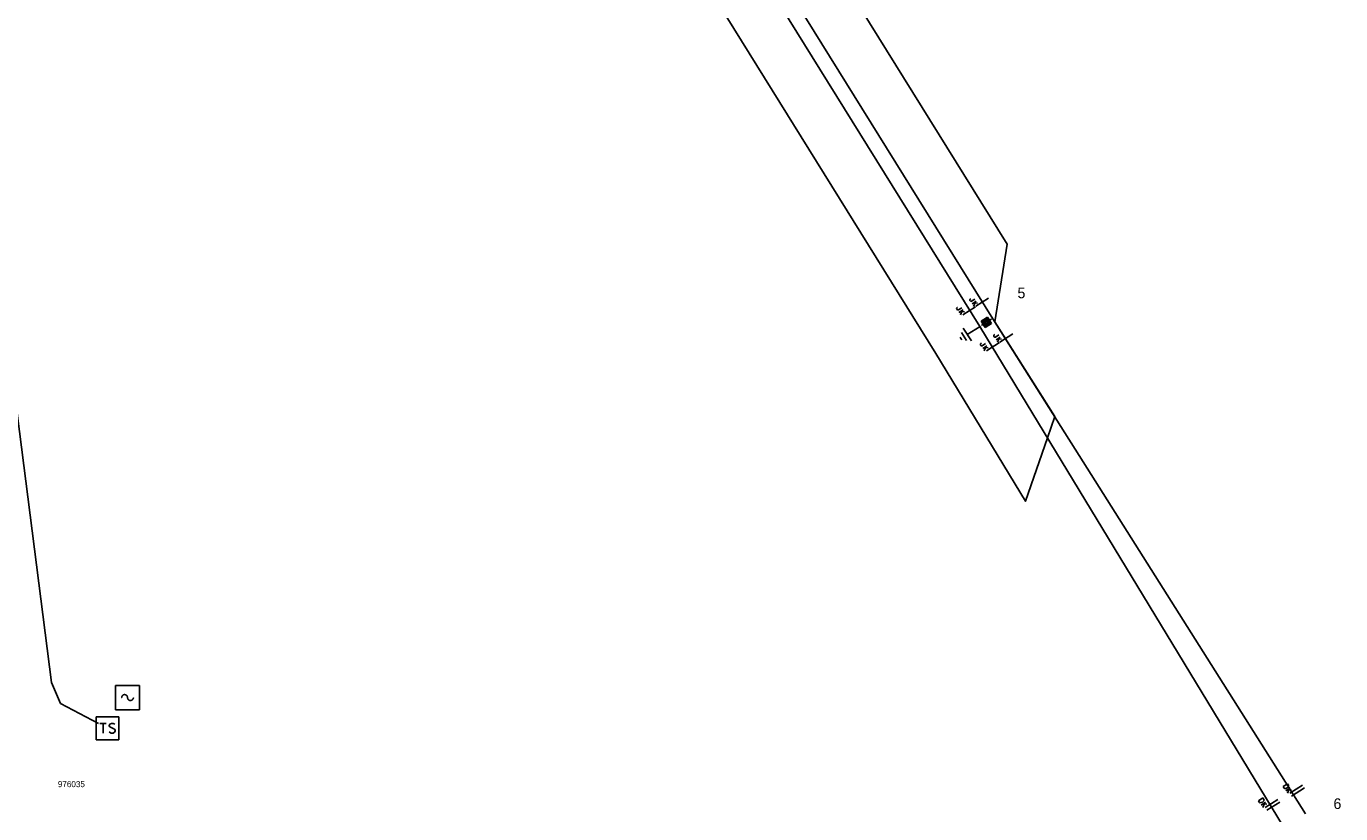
# Model space of a CAD drawing. Extents: x -788491 to -785797, y -1154753 to -1152002.
# Drawn here: x -787504.8 to -787287.9, y -1153999.5 to -1153869.5 of the extents above; entities that cross this region are included whole.
import ezdxf

# ---------------------------------------------------------------- set-up
doc = ezdxf.new("R2010")
doc.units = 0
for name, color, linetype in [('Vrstva 1', 7, 'Continuous'), ('Vrstva 13', 7, 'Continuous'), ('Vrstva 14', 7, 'Continuous'), ('Vrstva 15', 7, 'Continuous'), ('Vrstva 18', 7, 'Continuous'), ('Vrstva 2', 7, 'Continuous'), ('Vrstva 25', 7, 'Continuous'), ('Vrstva 26', 7, 'Continuous'), ('Vrstva 34', 7, 'Continuous'), ('Vrstva 35', 7, 'Continuous'), ('Vrstva 5', 7, 'Continuous'), ('Vrstva 6', 7, 'Continuous')]:
    doc.layers.add(name, color=color, linetype=linetype)

# ---------------------------------------------------------------- blocks, each defined once
blk = doc.blocks.new('VN850')
at = {"layer": 'Vrstva 15'}
for points in [[(-0.56, 1.43), (-0.56, -1.07)], [(-0.01, 1.43), (-0.01, -1.07)], [(-2.09, -0.54), (-1.78, -0.54)], [(-2.09, -1.41), (-2.09, -0.54)], [(-1.78, -1.41), (-2.09, -1.41)], [(-1.78, -0.54), (-1.66, -0.6)], [(-1.67, -1.35), (-1.78, -1.41)], [(-1.59, -1.2), (-1.67, -1.35)], [(-1.66, -0.6), (-1.59, -0.75)], [(-1.59, -0.75), (-1.55, -0.96)], [(-1.55, -0.96), (-1.59, -1.2)], [(-1.26, -0.54), (-1.26, -1.41)], [(-0.85, -0.54), (-1.26, -1.09)], [(-1.13, -0.92), (-0.77, -1.41)]]:
    blk.add_lwpolyline(points, dxfattribs=at)
blk = doc.blocks.new('VN840')
at = {"layer": 'Vrstva 15'}
for points in [[(-0.01, 1.41), (-0.01, -1.09)], [(-1.51, -1.24), (-1.51, -1.15)], [(-1.48, -1.35), (-1.51, -1.24)], [(-1.33, -1.42), (-1.48, -1.35)], [(-1.27, -1.42), (-1.33, -1.42)], [(-1.13, -1.35), (-1.27, -1.42)], [(-1.09, -1.24), (-1.13, -1.35)], [(-1.09, -0.59), (-1.09, -1.24)], [(-0.68, -0.59), (-0.68, -1.42)], [(-0.68, -1.11), (-0.27, -0.59)], [(-0.54, -0.94), (-0.2, -1.42)]]:
    blk.add_lwpolyline(points, dxfattribs=at)
blk = doc.blocks.new('VN810')
at = {"layer": 'Vrstva 14'}
for points in [[(0, -1.25), (0, -3.75)], [(1.25, -3.75), (-1.25, -3.75)], [(0.77, -4.37), (-0.8, -4.37)], [(0, -5), (-0.25, -5)], [(0.27, -5), (0, -5)]]:
    blk.add_lwpolyline(points, dxfattribs=at)
blk = doc.blocks.new('VN740')
at = {"layer": 'Vrstva 1'}
for points in [[(2, 2), (-2, 2)], [(-2, 2), (-2, -2)], [(0, 0), (0, 0.05), (-0.01, 0.1), (-0.02, 0.15), (-0.04, 0.2), (-0.06, 0.24), (-0.09, 0.29), (-0.12, 0.33), (-0.16, 0.36), (-0.2, 0.4), (-0.24, 0.42), (-0.29, 0.45), (-0.34, 0.47), (-0.38, 0.48), (-0.44, 0.49), (-0.49, 0.49), (-0.54, 0.49), (-0.59, 0.48), (-0.64, 0.47), (-0.69, 0.45), (-0.73, 0.43), (-0.77, 0.4), (-0.81, 0.37), (-0.85, 0.33), (-0.88, 0.29), (-0.91, 0.25), (-0.93, 0.2), (-0.95, 0.16), (-0.97, 0.11), (-0.97, 0.06), (-0.98, 0), (-0.98, 0)], [(2, -2), (2, 2)], [(-2, -2), (2, -2)], [(0, 0), (0, -0.05), (0.01, -0.1), (0.02, -0.15), (0.04, -0.2), (0.06, -0.24), (0.09, -0.28), (0.12, -0.32), (0.15, -0.36), (0.19, -0.39), (0.23, -0.42), (0.28, -0.44), (0.32, -0.46), (0.37, -0.48), (0.42, -0.49), (0.47, -0.49), (0.52, -0.49), (0.57, -0.48), (0.62, -0.47), (0.67, -0.45), (0.71, -0.43), (0.75, -0.4), (0.79, -0.37), (0.83, -0.34), (0.86, -0.3), (0.89, -0.26), (0.91, -0.21), (0.93, -0.17), (0.95, -0.12), (0.96, -0.07), (0.96, -0.02), (0.96, -0.02)]]:
    blk.add_lwpolyline(points, dxfattribs=at)
blk = doc.blocks.new('VN640')
at = {"layer": 'Vrstva 6'}
for points in [[(-1.89, 1.89), (1.89, 1.89)], [(-1.89, -1.89), (-1.89, 1.89)], [(-1.26, 0.79), (-0.22, 0.79)], [(-0.73, 0.79), (-0.73, -0.79)], [(1.2, 0.66), (0.94, 0.79), (0.66, 0.79), (0.41, 0.66), (0.28, 0.47), (0.28, 0.41), (0.41, 0.22), (1.13, -0.16), (1.26, -0.32), (1.26, -0.47), (1.13, -0.66), (0.91, -0.79), (0.63, -0.79), (0.5, -0.73), (0.28, -0.6)], [(1.89, 1.89), (1.89, -1.89)], [(1.89, -1.89), (-1.89, -1.89)]]:
    blk.add_lwpolyline(points, dxfattribs=at)
blk = doc.blocks.new('VN470')
at = {"layer": 'Vrstva 2'}
for points in [[(-1.23, 1.22), (1.23, 1.22)], [(-1.23, -1.23), (-1.23, 1.22)], [(-0.92, 0.9), (0.92, 0.9)], [(-0.92, -0.95), (-0.92, 0.9)], [(-0.61, 0.61), (0.61, 0.61)], [(-0.61, -0.62), (-0.61, 0.61)], [(-0.31, -0.27), (-0.31, 0.34)], [(-0.31, 0.34), (0.31, 0.34)], [(0, 1.22), (0, 1.97)], [(0.31, 0.34), (0.31, -0.27)], [(0.61, 0.61), (0.61, -0.62)], [(0.92, 0.9), (0.92, -0.95)], [(1.23, 1.22), (1.23, -1.23)], [(1.23, -1.23), (-1.23, -1.23)], [(0.92, -0.95), (-0.92, -0.95)], [(0.61, -0.62), (-0.61, -0.62)], [(0.31, -0.27), (-0.31, -0.27)], [(0, -1.23), (0, -1.98)]]:
    blk.add_lwpolyline(points, dxfattribs=at)

msp = doc.modelspace()

# ---------------------------------------------------------------- linework, layer by layer
at = {"layer": 'Vrstva 1'}
for points in [[(-787293.67, -1153999.52), (-787345.26, -1153917.76), (-787416.49, -1153803.15)], [(-787297.28, -1154001.71), (-787347.42, -1153919.07), (-787418.52, -1153804.59)]]:
    msp.add_lwpolyline(points, dxfattribs=at)
at = {"layer": 'Vrstva 35'}
msp.add_lwpolyline([(-787401.95, -1153763.53), (-787397.07, -1153772.71), (-787399.21, -1153776.96), (-787399.58, -1153777.84), (-787408.01, -1153800.68), (-787342.91, -1153905.45), (-787344.94, -1153918.29), (-787335.06, -1153933.94), (-787336.27, -1153937.46), (-787339.86, -1153947.92), (-787354.67, -1153923.51), (-787402.67, -1153846.22), (-787395.85, -1153841.11), (-787393.84, -1153839.6), (-787416.49, -1153803.15), (-787417.73, -1153802.45), (-787423.45, -1153799.21), (-787423.17, -1153789.6), (-787422.23, -1153790.13), (-787415.18, -1153771.09), (-787414.79, -1153770.21), (-787414.57, -1153769.76), (-787406.84, -1153754.33)], close=True, dxfattribs=at)
at = {"layer": 'Vrstva 5'}
msp.add_lwpolyline([(-787524.62, -1153931.18), (-787522.25, -1153931.23), (-787506.67, -1153930.76), (-787500.63, -1153977.83), (-787499.16, -1153981.29), (-787492.91, -1153984.61)], dxfattribs=at)

# ---------------------------------------------------------------- block references
at = {"layer": 'Vrstva 13', "xscale": 0.5, "yscale": 0.5, "rotation": -57.54109164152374}
msp.add_blockref('VN470', (-787346.33, -1153918.36), dxfattribs=at)
at = {"layer": 'Vrstva 15', "rotation": -57.42507771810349}
msp.add_blockref('VN810', (-787346.33, -1153918.36), dxfattribs=at)
at = {"layer": 'Vrstva 18'}
for name, p, rotation in [('VN840', (-787347.15, -1153915.13), -57.5410944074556), ('VN840', (-787349.32, -1153916.55), -57.528674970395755), ('VN840', (-787345.38, -1153922.48), -57.5771472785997), ('VN840', (-787343.18, -1153921.05), -57.541091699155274), ('VN850', (-787295.05, -1153996.03), -57.54109164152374), ('VN850', (-787299.12, -1153998.39), -57.5771472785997)]:
    msp.add_blockref(name, p, dxfattribs=dict(at, rotation=rotation))
at = {"layer": 'Vrstva 25'}
msp.add_blockref('VN640', (-787491.41, -1153985.41), dxfattribs=at)
at = {"layer": 'Vrstva 34'}
msp.add_blockref('VN740', (-787488.1, -1153980.34), dxfattribs=at)

# ---------------------------------------------------------------- texts
at = {"layer": 'Vrstva 14'}
for s, p in [('5', (-787341.21, -1153914.39)), ('6', (-787289.05, -1153998.73))]:
    msp.add_text(s, height=1.75, dxfattribs=at).set_placement(p)
at = {"layer": 'Vrstva 26'}
msp.add_text('976035', height=1, dxfattribs=at).set_placement((-787499.6, -1153995.13))

doc.saveas('drawing.dxf')
